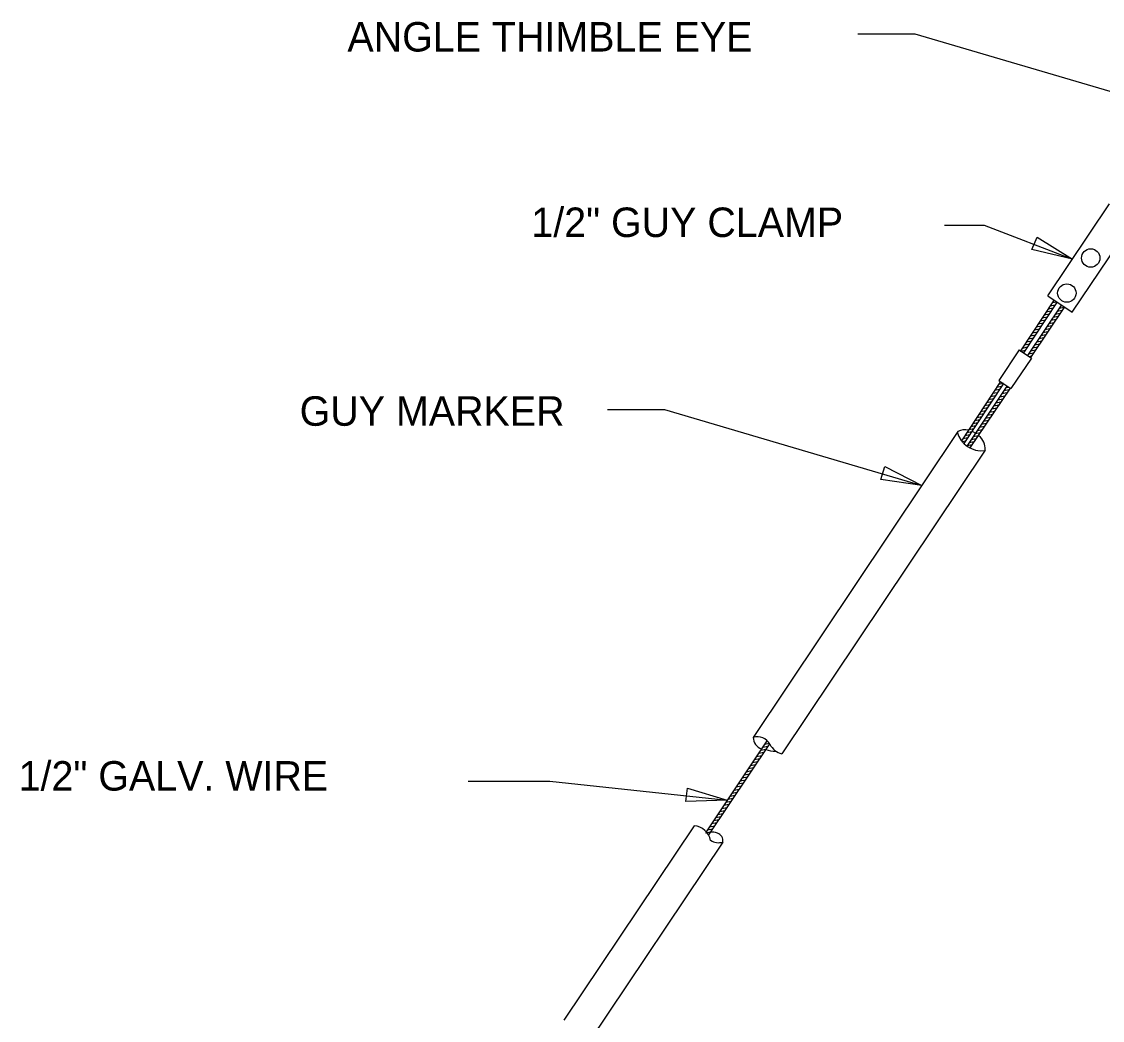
# Model space of a CAD drawing. Extents: x 1299104.8 to 1299141.6, y 239639.8 to 239661.8.
# Drawn here: x 1299115.921 to 1299120.323, y 239648.973 to 239653.039 of the extents above; entities that cross this region are included whole.
import ezdxf

# ---------------------------------------------------------------- set-up
doc = ezdxf.new("R2010")
doc.units = 0
doc.layers.add('DIM TXT', color=7, linetype='Continuous')

msp = doc.modelspace()

# ---------------------------------------------------------------- linework, layer by layer
at = {"layer": 'DIM TXT'}
for p, q in [((1299119.3273, 239652.9893), (1299119.5594, 239652.9893)), ((1299119.5594, 239652.9893), (1299120.6069, 239652.68)), ((1299120.1004, 239651.923), (1299120.3512, 239652.2966)), ((1299119.6799, 239652.2106), (1299119.8414, 239652.2106)), ((1299119.8414, 239652.2106), (1299120.2004, 239652.072)), ((1299120.2001, 239651.8561), (1299120.4509, 239652.2298)), ((1299120.1259, 239651.9059), (1299119.9895, 239651.6987)), ((1299120.1384, 239651.8977), (1299120.002, 239651.6903)), ((1299120.1004, 239651.923), (1299120.2001, 239651.8561)), ((1299120.1184, 239651.8946), (1299120.1391, 239651.8986)), ((1299120.1556, 239651.8859), (1299120.0177, 239651.6798)), ((1299120.1681, 239651.8776), (1299120.0301, 239651.6714)), ((1299120.086, 239651.8454), (1299120.1067, 239651.8494)), ((1299120.0941, 239651.8577), (1299120.1148, 239651.8617)), ((1299120.1022, 239651.87), (1299120.1229, 239651.874)), ((1299120.1103, 239651.8823), (1299120.131, 239651.8863)), ((1299120.1301, 239651.8478), (1299120.1509, 239651.8519)), ((1299120.1384, 239651.8602), (1299120.1592, 239651.8643)), ((1299120.1467, 239651.8727), (1299120.1675, 239651.8768)), ((1299120.0536, 239651.7961), (1299120.0743, 239651.8002)), ((1299120.0617, 239651.8084), (1299120.0824, 239651.8125)), ((1299120.0698, 239651.8207), (1299120.0905, 239651.8248)), ((1299120.0779, 239651.8331), (1299120.0986, 239651.8371)), ((1299120.0968, 239651.798), (1299120.1175, 239651.8021)), ((1299120.1051, 239651.8104), (1299120.1259, 239651.8145)), ((1299120.1134, 239651.8229), (1299120.1342, 239651.827)), ((1299120.1218, 239651.8353), (1299120.1425, 239651.8394)), ((1299120.0294, 239651.7592), (1299120.05, 239651.7633)), ((1299120.0375, 239651.7715), (1299120.0581, 239651.7756)), ((1299120.0456, 239651.7838), (1299120.0662, 239651.7879)), ((1299120.0718, 239651.7606), (1299120.0925, 239651.7647)), ((1299120.0801, 239651.7731), (1299120.1009, 239651.7772)), ((1299120.0884, 239651.7855), (1299120.1092, 239651.7896)), ((1299119.997, 239651.71), (1299120.0176, 239651.7141)), ((1299120.0051, 239651.7223), (1299120.0257, 239651.7264)), ((1299120.0132, 239651.7346), (1299120.0338, 239651.7387)), ((1299120.0213, 239651.7469), (1299120.0419, 239651.751)), ((1299120.0384, 239651.7108), (1299120.0592, 239651.7149)), ((1299120.0468, 239651.7233), (1299120.0676, 239651.7274)), ((1299120.0551, 239651.7357), (1299120.0759, 239651.7398)), ((1299120.0634, 239651.7482), (1299120.0842, 239651.7523)), ((1299119.9839, 239651.7025), (1299119.9003, 239651.5779)), ((1299120.0337, 239651.669), (1299119.9501, 239651.5445)), ((1299119.9839, 239651.7025), (1299120.0337, 239651.669)), ((1299119.9889, 239651.6977), (1299120.0095, 239651.7018)), ((1299120.0218, 239651.6859), (1299120.0426, 239651.69)), ((1299120.024, 239651.6756), (1299120.0342, 239651.6776)), ((1299120.0301, 239651.6984), (1299120.0509, 239651.7025)), ((1299119.9071, 239651.5734), (1299119.7485, 239651.3325)), ((1299119.9195, 239651.565), (1299119.7588, 239651.3208)), ((1299119.9342, 239651.5552), (1299119.7707, 239651.3108)), ((1299119.9467, 239651.5468), (1299119.7835, 239651.3029)), ((1299119.8836, 239651.5378), (1299119.9042, 239651.5418)), ((1299119.8917, 239651.5501), (1299119.9123, 239651.5541)), ((1299119.8998, 239651.5624), (1299119.9204, 239651.5664)), ((1299119.9003, 239651.5779), (1299119.9501, 239651.5445)), ((1299119.9218, 239651.5365), (1299119.9426, 239651.5406)), ((1299119.9301, 239651.549), (1299119.9404, 239651.551)), ((1299119.8512, 239651.4886), (1299119.8718, 239651.4926)), ((1299119.8593, 239651.5009), (1299119.8799, 239651.5049)), ((1299119.8674, 239651.5132), (1299119.888, 239651.5172)), ((1299119.8755, 239651.5255), (1299119.8961, 239651.5295)), ((1299119.8885, 239651.4867), (1299119.9092, 239651.4908)), ((1299119.8968, 239651.4992), (1299119.9176, 239651.5033)), ((1299119.9051, 239651.5116), (1299119.9259, 239651.5157)), ((1299119.9135, 239651.5241), (1299119.9342, 239651.5282)), ((1299118.3074, 239651.4598), (1299118.5394, 239651.4598)), ((1299118.5394, 239651.4598), (1299119.587, 239651.1506)), ((1299119.8269, 239651.4516), (1299119.8476, 239651.4557)), ((1299119.835, 239651.4639), (1299119.8557, 239651.468)), ((1299119.8431, 239651.4762), (1299119.8638, 239651.4803)), ((1299119.8635, 239651.4494), (1299119.8842, 239651.4535)), ((1299119.8718, 239651.4619), (1299119.8926, 239651.4659)), ((1299119.8801, 239651.4743), (1299119.9009, 239651.4784)), ((1299119.7945, 239651.4024), (1299119.8152, 239651.4065)), ((1299119.8026, 239651.4147), (1299119.8233, 239651.4188)), ((1299119.8107, 239651.427), (1299119.8314, 239651.4311)), ((1299119.8188, 239651.4393), (1299119.8395, 239651.4434)), ((1299119.8301, 239651.3996), (1299119.8509, 239651.4037)), ((1299119.8385, 239651.4121), (1299119.8592, 239651.4161)), ((1299119.8468, 239651.4245), (1299119.8676, 239651.4286)), ((1299119.8551, 239651.437), (1299119.8759, 239651.441)), ((1299119.734, 239651.3703), (1299118.9004, 239650.1247)), ((1299119.7703, 239651.3655), (1299119.7909, 239651.3696)), ((1299119.7783, 239651.3778), (1299119.799, 239651.3819)), ((1299119.7864, 239651.3901), (1299119.8071, 239651.3942)), ((1299119.8051, 239651.3623), (1299119.8259, 239651.3663)), ((1299119.8135, 239651.3747), (1299119.8343, 239651.3788)), ((1299119.8218, 239651.3872), (1299119.8426, 239651.3912)), ((1299119.7508, 239651.3296), (1299119.7666, 239651.3327)), ((1299119.7541, 239651.3409), (1299119.7747, 239651.345)), ((1299119.7622, 239651.3532), (1299119.7828, 239651.3573)), ((1299119.7718, 239651.3125), (1299119.7926, 239651.3166)), ((1299119.7801, 239651.3249), (1299119.8009, 239651.329)), ((1299119.7885, 239651.3374), (1299119.8093, 239651.3415)), ((1299119.7968, 239651.3498), (1299119.8176, 239651.3539)), ((1299119.8448, 239651.2947), (1299119.0166, 239650.0573)), ((1299119.7821, 239651.3037), (1299119.7843, 239651.3041)), ((1299118.9564, 239650.1101), (1299118.7088, 239649.7401)), ((1299118.9671, 239650.0991), (1299118.7186, 239649.7278)), ((1299118.9394, 239650.0847), (1299118.9602, 239650.0888)), ((1299118.9478, 239650.0971), (1299118.9661, 239650.1008)), ((1299118.9061, 239650.0349), (1299118.9269, 239650.039)), ((1299118.9144, 239650.0473), (1299118.9352, 239650.0514)), ((1299118.9228, 239650.0598), (1299118.9436, 239650.0639)), ((1299118.9311, 239650.0722), (1299118.9519, 239650.0763)), ((1299118.8811, 239649.9976), (1299118.9019, 239650.0016)), ((1299118.8894, 239650.01), (1299118.9102, 239650.0141)), ((1299118.8978, 239650.0224), (1299118.9186, 239650.0265)), ((1299118.8478, 239649.9478), (1299118.8686, 239649.9518)), ((1299118.8561, 239649.9602), (1299118.8769, 239649.9643)), ((1299118.8644, 239649.9727), (1299118.8852, 239649.9767)), ((1299118.8728, 239649.9851), (1299118.8936, 239649.9892)), ((1299117.7396, 239649.9462), (1299118.072, 239649.9462)), ((1299118.072, 239649.9462), (1299118.7948, 239649.8685)), ((1299118.8228, 239649.9104), (1299118.8436, 239649.9145)), ((1299118.8311, 239649.9229), (1299118.8519, 239649.9269)), ((1299118.8394, 239649.9353), (1299118.8602, 239649.9394)), ((1299118.7895, 239649.8606), (1299118.8102, 239649.8647)), ((1299118.7978, 239649.8731), (1299118.8186, 239649.8772)), ((1299118.8061, 239649.8855), (1299118.8269, 239649.8896)), ((1299118.8145, 239649.898), (1299118.8352, 239649.902)), ((1299118.7645, 239649.8233), (1299118.7852, 239649.8274)), ((1299118.7728, 239649.8357), (1299118.7936, 239649.8398)), ((1299118.7811, 239649.8482), (1299118.8019, 239649.8523)), ((1299118.7311, 239649.7735), (1299118.7519, 239649.7776)), ((1299118.7395, 239649.7859), (1299118.7603, 239649.79)), ((1299118.7478, 239649.7984), (1299118.7686, 239649.8025)), ((1299118.7561, 239649.8108), (1299118.7769, 239649.8149)), ((1299118.6597, 239649.7651), (1299118.1295, 239648.973)), ((1299118.7061, 239649.7361), (1299118.7269, 239649.7402)), ((1299118.7114, 239649.7372), (1299118.7269, 239649.7402)), ((1299118.7145, 239649.7486), (1299118.7353, 239649.7527)), ((1299118.7228, 239649.761), (1299118.7436, 239649.7651)), ((1299118.7765, 239649.6986), (1299118.233, 239648.8864))]:
    msp.add_line(p, q, dxfattribs=at)
for points in [[(1299120.0358, 239652.1105), (1299120.0566, 239652.1607), (1299120.2004, 239652.072)], [(1299119.4198, 239651.1753), (1299119.4362, 239651.2271), (1299119.587, 239651.1506)], [(1299118.6258, 239649.8636), (1299118.633, 239649.9174), (1299118.7948, 239649.8685)]]:
    msp.add_lwpolyline(points, close=True, dxfattribs=at)
for centre in [(1299120.2755, 239652.0764), (1299120.178, 239651.9335)]:
    msp.add_circle(centre, 0.0375, dxfattribs=at)
for centre, radius, start, end in [((1299119.8308, 239651.3945), 0.103, 195.6592, 276.8488), ((1299119.7621, 239651.3179), 0.0595, 75.6801, 118.1545), ((1299119.7438, 239651.2601), 0.1199, 59.0012, 66.6673), ((1299119.7438, 239651.2601), 0.1199, 50.4285, 51.8273), ((1299119.7765, 239651.2998), 0.0684, 355.6621, 50.6246), ((1299118.918, 239650.0709), 0.0566, 26.9276, 108.1763), ((1299118.9511, 239650.1257), 0.0507, 181.067, 251.2118), ((1299119.0371, 239650.1314), 0.0769, 206.9276, 254.5493), ((1299118.9894, 239650.1898), 0.1209, 251.72, 271.3267), ((1299118.6509, 239649.6872), 0.0784, 13.5077, 83.5679), ((1299118.7363, 239649.7016), 0.0376, 61.0749, 107.216), ((1299118.7459, 239649.7045), 0.0312, 349.0501, 73.9414), ((1299118.7592, 239649.7543), 0.0583, 236.7201, 287.3061)]:
    msp.add_arc(centre, radius, start, end, dxfattribs=at)

# ---------------------------------------------------------------- texts
for s, p in [('ANGLE THIMBLE EYE', (1299117.2477, 239652.9171)), ('1/2" GUY CLAMP', (1299117.9969, 239652.1619)), ('GUY MARKER', (1299117.0532, 239651.3934)), ('1/2" GALV. WIRE', (1299115.9085, 239649.908))]:
    msp.add_text(s, height=0.12, dxfattribs=at).set_placement(p)

doc.saveas('drawing.dxf')
